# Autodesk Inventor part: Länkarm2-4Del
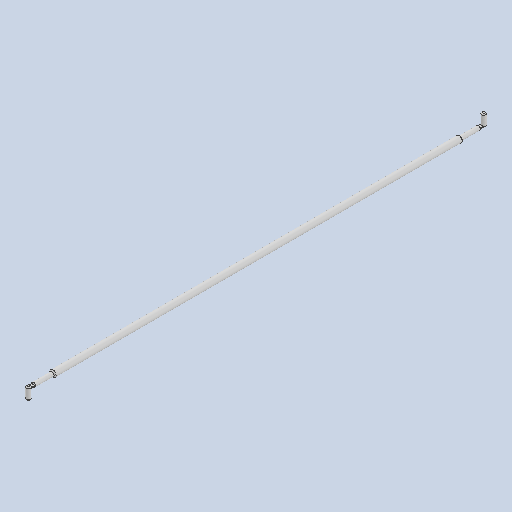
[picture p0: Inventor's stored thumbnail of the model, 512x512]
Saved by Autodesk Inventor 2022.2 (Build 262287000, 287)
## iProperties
Created: 2022-03
Part Number: Länkarm2-4Del
Material: Generic
Document SubType Name: Modeling
Designer: cl
Density: 1 g/cm^3
Appearance: Default
Author: cl
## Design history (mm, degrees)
sketch "Sketch1"
  geometry: L1 (0, 0)-(0, -2083.4); L2 (0, 0)-(-10, 0); L3 (-10, 0)-(-10, -90); L4 (-10, -90)-(-15, -90); L5 (-15, -90)-(-15, -1993.4); L6 (0, -2083.4)-(-10, -2083.4); L7 (-10, -2083.4)-(-10, -1993.4); L8 (-10, -1993.4)-(-15, -1993.4); 1 further point
  constraints: 16 end point, 5 perpendicular, 2 horizontal, 1 midpoint, 1 vertical
  dimensions: "d0" = 2083.4 distance of L1.start L1.end (computed from BladBredd); "d1" = 20 diameter of L3 L1; "d2" = 5 distance between parallel lines of L3 L5; "d3" = 90 distance of L2.end L3.end; "d4" = 20 diameter of L7 L1; "d5" = 90 vertical distance of point (-5, -2083.4) L5.end
revolve "Revolution1" sketch "Sketch1" stored, may be unused: angle "d6" = 90 deg
fillet "Fillet1" dims "d7" = 5
workplane "Work Plane1"
sketch "Sketch2"
  geometry: L1 (10, 0)-(-10, 0) reference; L2 (7.5, 0)-(-7.5, 0); L3 (-7.5, 0)-(-7.5, 20); L4 (-7.5, 20)-(7.5, 20); L5 (7.5, 20)-(7.5, 0); L6 (10, -90)-(10, 0) reference; L7 (10, -2083.4)-(-10, -2083.4) reference; L8 (7.5, -2083.4)-(-7.5, -2083.4); L9 (-7.5, -2083.4)-(-7.5, -2103.4); L10 (-7.5, -2103.4)-(7.5, -2103.4); L11 (7.5, -2103.4)-(7.5, -2083.4); 3 further points
  constraints: 16 end point, 4 parallel, 2 horizontal, 2 perpendicular, 2 point on line, 1 collinear
  dimensions: "d9" = 2.5 distance between parallel lines of L5 L6; "d10" = 15 distance of L3.end L4.end; "d11" = 20 distance of L2.end L3.end; "d12" = 20 distance of L8.end L9.end; "d13" = 15 distance of L9.end L10.end
extrude "Extrusion1" join sketch "Sketch2" distance "d14" = 4; taper "d15" = 0 deg
sketch "Sketch3"
  geometry: L1 (7.5, 20)-(-7.5, 20) reference; L2 (-7.5, -2103.4)-(7.5, -2103.4) reference; C1 r 10 at (0, 20); C2 r 10 at (0, -2103.4); 1 further point
  constraints: 2 centre point, 2 midpoint
  dimensions: "d16" = 20 diameter of C1; "d17" = 20 diameter of C2
extrude "Extrusion2" join sketch "Sketch3" distance "d18" = 8; taper "d20" = 0 deg; dims "d19" = 48, "d21" = 0
extrude "Extrusion3" join sketch "Sketch3" distance "d22" = 50; taper "d24" = 0 deg; dims "d23" = 6, "d25" = 0
fillet "Fillet2" dims "d26" = 5
body "Solid1"
other parameters: "BladBredd" = 987.5, "Fönsterhöjd" = 862, "Blad2" = 1012.5, "Blad3" = 0, "Blad4" = 0, "Blad5" = 1012.5, "Blad6" = 2025, "MGJ12Djup" = 0, "MGJ12Bredd" = 0, "MGJ2Djup" = 0, "MGJ2Bredd" = 5012.5, "MGJ56Djup" = 0, "MGJ56Bredd" = 0, "MGJ23Djup" = 48, "MGJ45Djup" = 48, "GarageRegel5" = 0, "GarageRegel6" = 0, "Styrrulle2Djup" = 0, "FönsterhöjdStyrning" = 862, "FönsterKarm" = 54, "AndraGlasraden" = 0, "BrösthöjdStyrning2" = 0.0001, "InfälldGångDörr" = 0, "Infälldstyr" = 1012.5, "EnDelGångDörr" = 0, "VinkelJärnStyrSkena" = 1456.25, "d8" = -2
